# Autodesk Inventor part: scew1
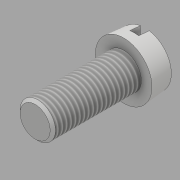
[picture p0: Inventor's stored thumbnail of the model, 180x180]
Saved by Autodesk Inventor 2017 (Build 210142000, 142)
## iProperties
Created: 2016-05
Part Number: scew1
Material: Generic
Document SubType Name: Modeling
Designer: CADCIM
Density: 1 g/cm^3
Appearance: Default
Author: CADCIM
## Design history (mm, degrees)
sketch "Sketch1"
  geometry: C1 r 9.6 at (0, 0); 1 further point
  constraints: 1 centre point, 1 coincident
  dimensions: "d0" = 19.2 diameter of C1
extrude "Extrusion1" new body sketch "Sketch1" distance "d1" = 7.2; taper "d2" = -5 deg
sketch "Sketch3"
  geometry: C1 r 6 at (0, 0); 1 further point
  constraints: 1 centre point, 1 coincident
  dimensions: "d7" = 12 diameter of C1
extrude "Extrusion3" join sketch "Sketch3" distance "d8" = 30; taper "d9" = 0 deg
thread "Thread1" dims "d13" = 10, "d14" = 0
chamfer "Chamfer2" distance "d15" = 0.9; stored, may be unused: second distance "d16" = 2, angle "d17" = 45 deg
sketch "Sketch4"
  geometry: L1 (1.5, -10.35)-(-1.5, -10.35); L2 (-1.5, -10.35)-(-1.5, 10.35); L3 (-1.5, 10.35)-(1.5, 10.35); L4 (1.5, 10.35)-(1.5, -10.35); L5 (0, -10.35)-(0, 10.35); 2 further points
  constraints: 10 end point, 3 midpoint, 2 parallel, 1 coincident, 1 horizontal, 1 perpendicular
  dimensions: "d18" = 3 distance of L1.start L1.end
extrude "Extrusion4" cut sketch "Sketch4" distance "d19" = 3.6; taper "d20" = 0 deg
body "Solid1"
